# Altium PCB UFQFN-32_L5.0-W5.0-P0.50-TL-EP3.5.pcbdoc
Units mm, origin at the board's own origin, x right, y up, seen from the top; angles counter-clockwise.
Board outline 18.72 x 18.5 mm, 2 copper layers (Top Layer, Bottom Layer), stack 0 mm thick; 1 components, 0 nets, 33 pads, 0 vias.
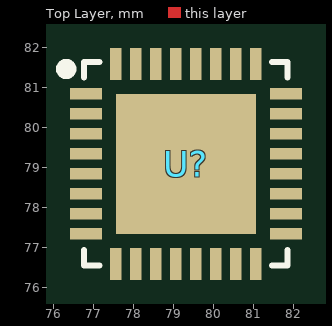
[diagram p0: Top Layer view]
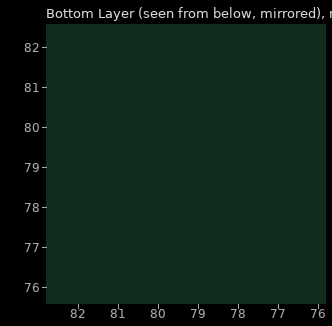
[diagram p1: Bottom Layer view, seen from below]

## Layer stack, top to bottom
Top Layer: signal copper (thickness not stored)
Bottom Layer: signal copper (thickness not stored)

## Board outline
88.567,69.85 69.85,69.85 69.85,88.35 88.567,88.35

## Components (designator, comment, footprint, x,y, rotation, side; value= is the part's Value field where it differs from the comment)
U? "" UFQFN-32_L5.0-W5.0-P0.50-TL-EP3.5 79.317,79.1 r0 top

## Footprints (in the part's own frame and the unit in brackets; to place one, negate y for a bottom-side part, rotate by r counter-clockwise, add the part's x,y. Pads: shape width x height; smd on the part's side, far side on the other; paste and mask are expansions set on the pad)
UFQFN-32_L5.0-W5.0-P0.50-TL-EP3.5 [mm]
  rect 0.8x0.28 smd paste-100 mask+0.051: 1(-2.5,1.75) 2(-2.5,1.25) 3(-2.5,0.75) 4(-2.5,0.25) 5(-2.5,-0.25) 6(-2.5,-0.75) 7(-2.5,-1.25) 8(-2.5,-1.75) 17(2.5,-1.75) 18(2.5,-1.25) 19(2.5,-0.75) 20(2.5,-0.25) 21(2.5,0.25) 22(2.5,0.75) 23(2.5,1.25) 24(2.5,1.75)
  rect 0.28x0.8 smd paste-100 mask+0.051: 9(-1.75,-2.5) 10(-1.25,-2.5) 11(-0.75,-2.5) 12(-0.25,-2.5) 13(0.25,-2.5) 14(0.75,-2.5) 15(1.25,-2.5) 16(1.75,-2.5) 25(1.75,2.5) 26(1.25,2.5) 27(0.75,2.5) 28(0.25,2.5) 29(-0.25,2.5) 30(-0.75,2.5) 31(-1.25,2.5) 32(-1.75,2.5)
  rect 3.5x3.5 smd paste-100 mask+0.051: 33(0,0)
  silkscreen extent -3.12,-2.54 2.54,2.54

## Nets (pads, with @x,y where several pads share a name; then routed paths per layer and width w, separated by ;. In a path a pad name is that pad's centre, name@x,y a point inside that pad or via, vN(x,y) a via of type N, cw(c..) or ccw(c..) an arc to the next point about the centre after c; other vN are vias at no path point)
pads on no net: U?.1 U?.2 U?.3 U?.4 U?.5 U?.6 U?.7 U?.8 U?.9 U?.10 U?.11 U?.12 U?.13 U?.14 U?.15 U?.16 U?.17 U?.18 U?.19 U?.20 U?.21 U?.22 U?.23 U?.24 U?.25 U?.26 U?.27 U?.28 U?.29 U?.30 U?.31 U?.32 U?.33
